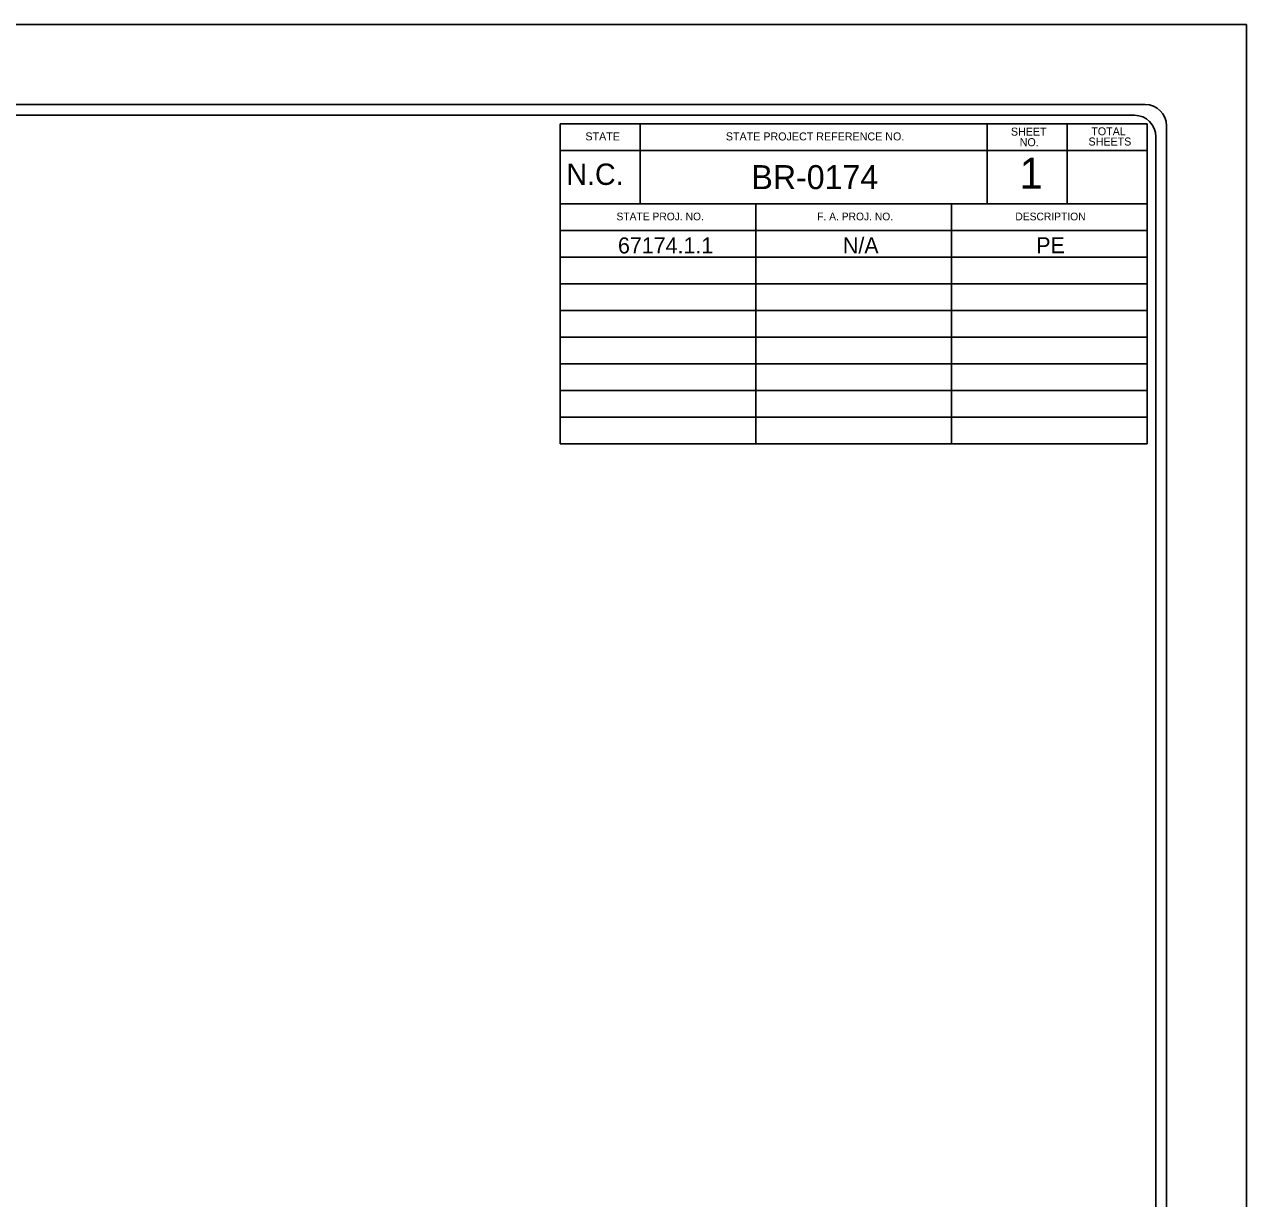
# Model space of a CAD drawing. Extents: x 24 to 7314, y 15 to 1598.
# Drawn here: x 6742 to 7314, y 1048 to 1598 of the extents above; entities that cross this region are included whole.
import ezdxf

# ---------------------------------------------------------------- set-up
doc = ezdxf.new("R2010")
doc.units = 0
for name, color, linetype in [('Prop DSN Text', 7, 'Continuous'), ('Sheet Title Data Points CELL', 7, 'Continuous'), ('Sheet_Sticker_Incomplete_CELL', 7, 'Continuous')]:
    doc.layers.add(name, color=color, linetype=linetype)

msp = doc.modelspace()

# ---------------------------------------------------------------- linework, layer by layer
at = {"layer": 'Prop DSN Text'}
for p, q in [((7266.73, 1560.9), (5661.73, 1560.9)), ((7261.73, 1555.83), (5716.73, 1555.83)), ((7267.73, 1551.87), (6992.73, 1551.86)), ((6992.73, 1551.86), (6992.73, 1401.87)), ((7030.23, 1514.36), (7030.23, 1551.87)), ((7030.23, 1551.87), (7192.74, 1551.86)), ((7192.74, 1551.86), (7192.73, 1514.37)), ((7267.73, 1551.87), (7230.23, 1551.87)), ((7230.23, 1551.87), (7230.24, 1514.37)), ((7267.73, 1539.37), (7267.73, 1551.87)), ((7267.73, 1401.87), (7267.73, 1551.87)), ((7271.73, 735.84), (7271.73, 1545.83)), ((7276.73, 545.9), (7276.73, 1550.9)), ((6992.73, 1514.37), (6992.73, 1539.37)), ((6992.73, 1539.37), (7267.73, 1539.37)), ((7267.73, 1514.37), (6992.73, 1514.37)), ((7084.38, 1514.36), (7030.23, 1514.36)), ((7084.38, 1401.86), (7084.38, 1514.36)), ((7192.73, 1514.37), (7176.03, 1514.37)), ((7176.03, 1514.37), (7176.03, 1401.87)), ((7267.73, 1501.86), (7267.73, 1514.37)), ((6992.73, 1489.36), (6992.73, 1501.86)), ((6992.73, 1501.86), (7267.73, 1501.86)), ((7267.73, 1489.36), (6992.73, 1489.36)), ((7267.73, 1476.87), (7267.73, 1489.36)), ((6992.73, 1476.86), (7267.73, 1476.87)), ((6992.73, 1464.37), (6992.73, 1476.86)), ((7267.73, 1464.37), (6992.73, 1464.37)), ((7267.73, 1451.87), (7267.73, 1464.37)), ((6992.74, 1439.36), (6992.73, 1451.87)), ((6992.73, 1451.87), (7267.73, 1451.87)), ((7267.73, 1439.36), (6992.74, 1439.36)), ((7267.73, 1426.86), (7267.73, 1439.36)), ((6992.73, 1414.37), (6992.73, 1426.86)), ((6992.73, 1426.86), (7267.73, 1426.86)), ((7267.73, 1414.36), (6992.73, 1414.37)), ((7267.73, 1401.87), (7267.73, 1414.36)), ((6992.73, 1401.87), (7267.73, 1401.87)), ((6992.73, 1401.87), (7084.38, 1401.86)), ((7176.03, 1401.87), (7267.73, 1401.87))]:
    msp.add_line(p, q, dxfattribs=at)
for centre in [(7266.73, 1550.9), (7261.73, 1545.83)]:
    msp.add_arc(centre, 10, 360, 90, dxfattribs=at)
at = {"layer": 'Sheet_Sticker_Incomplete_CELL'}
for p, q in [((7314.23, 1598.4), (5614.23, 1598.4)), ((7314.23, 498.4), (7314.23, 1598.4))]:
    msp.add_line(p, q, dxfattribs=at)

# ---------------------------------------------------------------- texts
at = {"layer": 'Prop DSN Text'}
for s, height, p in [('STATE', 3.75, (7004.52, 1544.08)), ('STATE PROJECT REFERENCE NO.', 3.7498, (7070.32, 1544.07)), ('SHEET', 3.75, (7203.84, 1546.32)), ('TOTAL', 3.75, (7241.49, 1546.46)), ('NO.', 3.75, (7207.96, 1541.38)), ('SHEETS', 3.75, (7240.19, 1541.68)), ('1', 14.51, (7207.89, 1521.44)), ('N.C.', 10, (6995.63, 1523.23)), ('STATE PROJ. NO.', 3.6, (7019.08, 1506.65)), ('F. A. PROJ. NO.', 3.6, (7113.09, 1506.65)), ('DESCRIPTION', 3.6, (7205.92, 1506.64))]:
    msp.add_text(s, height=height, rotation=360, dxfattribs=at).set_placement(p)
at = {"layer": 'Sheet Title Data Points CELL'}
for s, height, p in [('  BR-0174 ', 11.25, (7073.94, 1521.24)), (' 67174.1.1', 7.5, (7016.99, 1491.14)), ('      N/A     ', 7.5, (7108.43, 1491.14)), ('    PE    ', 7.5, (7204.55, 1491.24))]:
    msp.add_text(s, height=height, rotation=360, dxfattribs=at).set_placement(p)

doc.saveas('drawing.dxf')
